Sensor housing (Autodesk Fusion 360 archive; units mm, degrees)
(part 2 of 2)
sketch "Schizzo79" plane through (0, 0, 0) normal (0, 1, 0) x axis (1, 0, 0)
  line L1 (-19.2594, 177.5) -> (-24, 177.5)
  line L2 (-19.2594, 175) -> (-19.2594, 177.5)
  line L3 (-24, 175) -> (-19.2594, 175)
  line L4 (-24, 177.5) -> (-24, 175)
  line L5 (0.3577, 175) -> (-23.5572, 175)
  line L6 (0.3577, 175) -> (8.3577, 175)
  line L7 (32.2725, 175) -> (8.3577, 175)
  line L8 (29.2382, 175) -> (32.2725, 175)
  line L9 (29.2382, 175) -> (29.5577, 175)
  line L10 (32.2725, 175) -> (29.2382, 175)
  line L11 (32.2725, 175) -> (8.3577, 175)
  line L12 (0.3577, 175) -> (8.3577, 175)
  line L13 (0.3577, 175) -> (-23.5572, 175)
  line L14 (-20.5229, 175) -> (-23.5572, 175)
  line L15 (-20.8423, 175) -> (-20.5229, 175)
  line L16 (-23.5572, 175) -> (-20.5229, 175)
  line L17 (42.3577, 175) -> (36.3577, 175)
  line L18 (-27.6423, 175) -> (-33.6423, 175)
  line L19 (38.7547, 175) -> (-30.0393, 175)
  line L20 (-30.0393, 175) -> (-38.1423, 175)
  line L21 (38.7547, 175) -> (-30.0393, 175)
  line L22 (46.8577, 175) -> (38.7547, 175)
  line L23 (4.3577, 190) -> (4.3577, 175)
  line L24 (32.7153, 175) -> (27.9747, 175)
  line L25 (32.7153, 177.5) -> (32.7153, 175)
  line L26 (27.9747, 177.5) -> (32.7153, 177.5)
  line L27 (27.9747, 175) -> (27.9747, 177.5)
  point P22 (4.3577, 175)
  point P2 (-24, 177.5)
  point P26 (32.7153, 177.5)
  point P3 (-19.2594, 177.5)
  point P27 (27.9747, 177.5)
  point P4 (-19.2594, 175)
  point P24 (27.9747, 175)
  point P5 (-24, 175)
  point P25 (32.7153, 175)
  horizontal L1
  vertical L2
  horizontal L3
  vertical L4
  midpoint L19 P22
  perpendicular L19 L23
  symmetric P2 L23 P26
  symmetric P3 L23 P27
  symmetric P4 L23 P24
  symmetric P5 L23 P25
  dimension "d338" distance P2 P5 = 2.5
revolve "Rivoluzione" sketch "Schizzo79" AlongAngle -15
circular_pattern "Serie C1" TotalAngle 360
fillet "Raccordo2" radius 1.25
sketch "Schizzo1" plane through (0, 0, -175) normal (0, 0, -1) x axis (1, 0, 0)
  line L1 (29.2382, 4.0232) -> (32.2725, 4.0232)
  line L2 (31.591, -7.2971) -> (28.6932, -6.5207)
  line L3 (8.3577, -24.8573) -> (8.3577, -27.8917)
  line L4 (-2.9352, -27.2174) -> (-2.1588, -24.3197)
  line L5 (-20.5229, -3.9768) -> (-23.5572, -3.9768)
  line L6 (-22.8872, 7.3003) -> (-19.9895, 6.5238)
  line L7 (0.3577, 24.9037) -> (0.3577, 27.9381)
  line L8 (11.6622, 27.2608) -> (10.8857, 24.363)
  line L9 (-2.9352, -27.2174) -> (-2.1588, -24.3197)
  line L10 (-2.0067, -23.7522) -> (-2.1588, -24.3197)
  line L11 (8.3577, -27.8917) -> (4, 0)
  line L12 (4, 0) -> (0.3577, -27.8917)
  line L13 (4, 0) -> (-2.9352, -27.2174)
  line L14 (4.1983, -0.0259) -> (0.556, -27.9176)
  line L15 (8.2589, -27.9071) -> (3.9012, -0.0154)
  arc A1 centre (4.3577, 0.0232) radius 28.2 clockwise from (11.6622, 27.2608) to (32.2725, 4.0232)
  arc A2 centre (4.3577, 0.0232) radius 25.2 clockwise from (29.2382, 4.0232) to (28.6932, -6.5207)
  arc A3 centre (4.3577, 0.0232) radius 28.2 clockwise from (31.591, -7.2971) to (8.3577, -27.8917)
  arc A4 centre (4.3577, 0.0232) radius 25.2 clockwise from (8.3577, -24.8573) to (-2.1588, -24.3197)
  arc A5 centre (4.3577, 0.0232) radius 28.2 clockwise from (-2.9352, -27.2174) to (-23.5572, -3.9768)
  arc A6 centre (4.3577, 0.0232) radius 25.2 clockwise from (-20.5229, -3.9768) to (-19.9895, 6.5238)
  arc A7 centre (4.3577, 0.0232) radius 28.2 clockwise from (-22.8872, 7.3003) to (0.3577, 27.9381)
  arc A8 centre (4.3577, 0.0232) radius 25.2 clockwise from (0.3577, 24.9037) to (10.8857, 24.363)
  arc A9 centre (4.3577, 0.0232) radius 35.2 clockwise from (-30.0393, 7.4989) to (38.7547, 7.4989)
  arc A10 centre (-30.6423, 0.0232) radius 7.5 clockwise from (-30.0393, -7.4525) to (-30.0393, 7.4989)
  arc A11 centre (4.3577, 0.0232) radius 35.2 clockwise from (38.7547, -7.4525) to (-30.0393, -7.4525)
  arc A12 centre (39.3577, 0.0232) radius 7.5 clockwise from (38.7547, 7.4989) to (38.7547, -7.4525)
  circle C1 centre (-30.6423, 0.0232) radius 3
  circle C2 centre (39.3577, 0.0232) radius 3
  circle C3 centre (4, 0) radius 24.5
  circle C4 centre (4, 0) radius 24.5
  circle C5 centre (4, 0) radius 28.1285
  point P25 (0.3577, -27.8917)
  point P10 (-2.1588, -24.3197)
  point P32 (-2.1588, -24.3197)
  point P33 (-2.0067, -23.7522)
  point P29 (4, 0)
  point P34 (4, 0)
  point P26 (8.3577, -27.8917)
  point P35 (8.3577, -27.8917)
  point P36 (0.3577, -27.8917)
  point P28 (4, 0)
  point P37 (4, 0)
  point P27 (-2.9352, -27.2174)
  point P38 (-2.9352, -27.2174)
  point P39 (4, 0)
  concentric C3 C5
  coincident P25 C5
  coincident P10 P32
  coincident C3 P33
  parallel L9 L10
  coincident P29 P34
  coincident P26 P35
  coincident P25 P36
  coincident P28 P37
  coincident P27 P38
  coincident P29 P39
  dimension "d344" = 0.2
  dimension "d345" = 0.1
extrude "Estrusione1" add sketch "Schizzo1" profile of A4 C3 C4 C5 L14 L15 along normal blind 2.3
fillet "Raccordo2" radius 1.25 1.25
circular_pattern "Serie C1" TotalAngle 360
combine "Combina1"
sketch "Schizzo81" plane through (0, 0, -33) normal (0, 0, -1) x axis (1, 0, 0)
  line L1 (5.2, -3.0082) -> (9, -3.0082)
  line L2 (5.2, 2.9918) -> (5.2, -3.0082)
  line L3 (9, 2.9918) -> (5.2, 2.9918)
  line L4 (9, -3.0082) -> (9, 2.9918)
  circle C1 centre (2, 0) radius 9
  circle C2 centre (-1, -0.0082) radius 5.1368
  circle C3 centre (8.1, 2) radius 0.75
  dimension "d356" diameter C3 = 1.5
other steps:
base_feature "Lavorazione di base1"
fillet "Raccordo1" radius 2.4
extrude "Estrusione11" cut sketch "Schizzo41" profile of L1 L2 L3 L4 distance 39
base_feature "Lavorazione di base1"
extrude "Estrusione9" cut sketch "Schizzo45" profile of C1 to an object
base_feature "Lavorazione di base1" bodies "Parte metallica"
base_feature "Lavorazione di base1"
extrude "Estrusione8" cut sketch "Schizzo48" profile of C3 C4 blind 4 from offset 2
create_component "CreaComponente1"
create_component "CreaComponente1"
remove_body "RimuoviCorpo1"
create_component "CreaComponente2"
create_component "CreaComponente3"
remove_body "RimuoviCorpo1"
create_component "CreaComponente4"
remove_body "RimuoviCorpo2"
create_component "CreaComponente5"
create_component "CreaComponente7"
remove_body "RimuoviCorpo3"
create_component "CreaComponente8"
create_component "CreaComponente9" sketch "Schizzo65"
create_component "CreaComponente10"
create_component "CreaComponente11"
remove_body "RimuoviCorpo2"
named bodies: "Parte metallica"

design "Connettore Sensori"
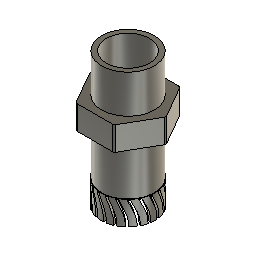
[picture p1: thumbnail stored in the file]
sketch "Schizzo1" plane through (0, 0, 0) normal (0, 0, 1) x axis (1, 0, 0)
  line L1 (4, 6.9282) -> (8, 0)
  line L2 (-4, 6.9282) -> (4, 6.9282)
  line L3 (-8, 0) -> (-4, 6.9282)
  line L4 (-4, -6.9282) -> (-8, 0)
  line L5 (4, -6.9282) -> (-4, -6.9282)
  line L6 (8, 0) -> (4, -6.9282)
  line L7 (22.5, 0) -> (1.75, 0)
  point P1 (0, 0)
  point P8 (0, 0)
  point P2 (8, 0)
  coincident P1 P8
  parallel L2 L7
  dimension "d1" distance P2 P8 = 8
  dimension "d17" AlongDistance = -4.2 (= "-5 mm + 0.8 mm")
  dimension "d18" TaperAngle = 0
extrude "Estrusione1" new body sketch "Schizzo1" profile of L1 L2 L3 L4 L5 L6 along normal blind 5
sketch "Schizzo2" plane through (0, 0, 5) normal (0, 0, 1) x axis (-1, 0, 0)
  line L1 (-8, 0) -> (-4, 6.9282)
  line L2 (-4, -6.9282) -> (-8, 0)
  line L3 (4, -6.9282) -> (-4, -6.9282)
  line L4 (8, 0) -> (4, -6.9282)
  line L5 (4, 6.9282) -> (8, 0)
  line L6 (-4, 6.9282) -> (4, 6.9282)
  circle C1 centre (0, 0) radius 5.5
  point P1 (0, 0)
  point P12 (0, 0)
  coincident P1 P12
  dimension "d8" diameter C1 = 11
extrude "Estrusione3" add sketch "Schizzo2" profile of C1 along normal blind 8
sketch "Schizzo3" plane through (0, 0, 0) normal (0, 0, -1) x axis (1, 0, 0)
  line L1 (-8, 0) -> (-4, 6.9282)
  line L2 (-4, -6.9282) -> (-8, 0)
  line L3 (4, -6.9282) -> (-4, -6.9282)
  line L4 (8, 0) -> (4, -6.9282)
  line L5 (4, 6.9282) -> (8, 0)
  line L6 (-4, 6.9282) -> (4, 6.9282)
  circle C1 centre (0, 0) radius 5.5
extrude "Estrusione4" add sketch "Schizzo3" profile of C1 along normal blind 10
hole "Foratura" HoleDepth 23 HoleDiameter 9 TipAngle 180
sketch "Schizzo4" plane through (0, 0, 5) normal (0, 0, 1) x axis (-1, 0, 0)
  line L1 (-8, 0) -> (-4, 6.9282)
  line L2 (-4, -6.9282) -> (-8, 0)
  line L3 (4, -6.9282) -> (-4, -6.9282)
  line L4 (8, 0) -> (4, -6.9282)
  line L5 (4, 6.9282) -> (8, 0)
  line L6 (-2.8, 10.7282) -> (2.8, 10.7282)
  line L7 (-2.8, 7.1426) -> (-2.8, 10.7282)
  line L8 (2.8, 10.7282) -> (2.8, 7.1426)
  line L9 (-2.8, 7.1426) -> (2.8, 7.1426)
  line L10 (-4, 6.9282) -> (4, 6.9282)
  circle C1 centre (0, 0) radius 5.5
  perpendicular L7 L9
fillet "Raccordo" radius 0.5
sketch "Schizzo5" plane through (0, 0, -10) normal (0, 0, -1) x axis (1, 0, 0)
  circle C1 centre (0, 0) radius 4.5
  circle C2 centre (0, 0) radius 5.5
  circle C3 centre (0, 0) radius 5
  dimension "d21" = -0.5
extrude "Estrusione6" new body sketch "Schizzo5" profile of C2 C3 along normal blind 5
offset_faces "FacceDiOffset" distance 0.1
sketch "Schizzo6" plane through (0, 0, 0) normal (0, 1, 0) x axis (1, 0, 0)
  line L1 (-5.6, 15) -> (5.6, 15)
  line L2 (-5.6, 10) -> (5.6, 10)
  curve K1 (0.9879, 12.7103) -> (0.9879, 15)
  curve K2 (0, 11.4835) -> (0.9879, 12.7103)
  curve K3 (-0.5681, 10) -> (0, 11.4835)
  curve K4 (-0.5681, 10) -> (0.9879, 15)
  curve K5 (-1.0681, 10) -> (0.4879, 15)
  curve K6 (0.4879, 12.7103) -> (0.4879, 15)
  curve K7 (-0.5, 11.4835) -> (0.4879, 12.7103)
  curve K8 (-1.0681, 10) -> (-0.5, 11.4835)
  line L3 (-5.6, 10.1852) -> (5.6, 10.1852)
  point P6 (0.9879, 15)
  point P9 (-0.5681, 10)
  coincident L1 P6
  coincident L2 P9
  dimension "d29" = 0.1852
  dimension "d27" R-Pattern1-uDistance = 0.5
  dimension "d28" R-Pattern1-vDistance = 0
emboss "Sbalzo" sketch "Schizzo6" Depth -1 Horizontal Distance 0 Vertical Distance 0 Rotation Angle 0
circular_pattern "Serie C" countU 20 TotalAngle 360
